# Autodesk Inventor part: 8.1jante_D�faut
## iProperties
Created: 2011-01
Part Number: 8.1jante_D�faut
Document SubType Name: Modeling
Designer: eric
Density: 1 g/cm^3
Mass: 113.684 g
Surface Area: 1044.9 cm^2
Volume: 113.684 cm^3
Author: eric
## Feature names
1. Base1
